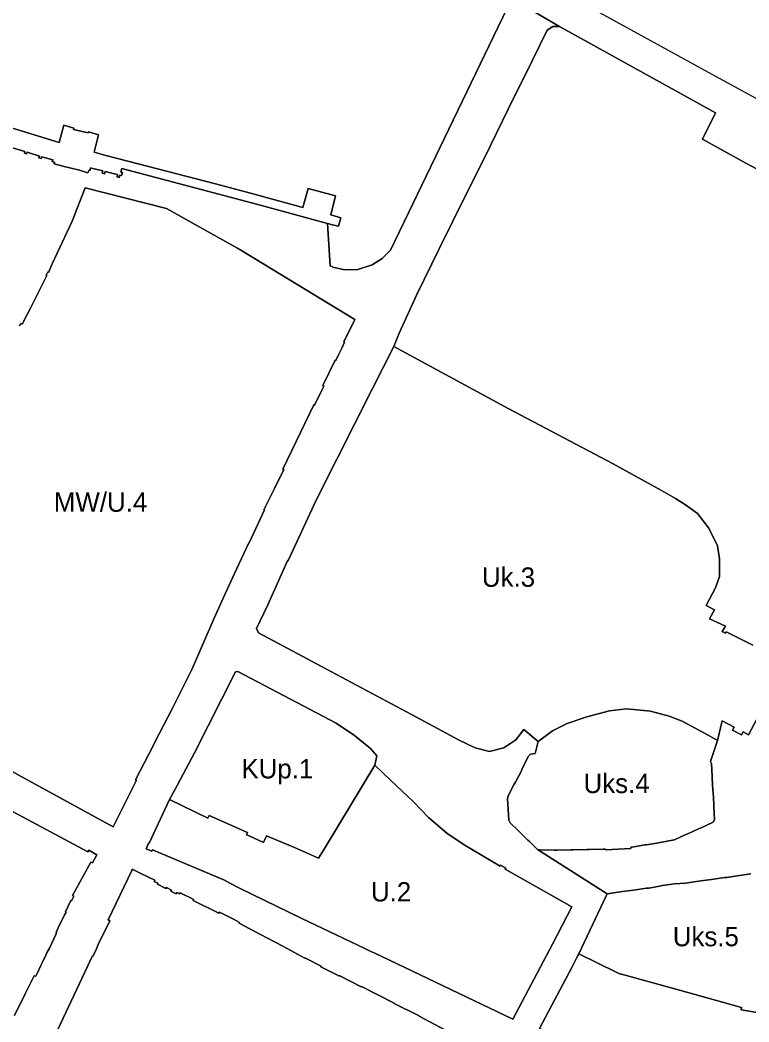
# Model space of a CAD drawing. Extents: x 7423367 to 7424726, y 5546744 to 5548391.
# Drawn here: x 7424194.2 to 7424382.5, y 5547946.7 to 5548205.6 of the extents above; entities that cross this region are included whole.
import ezdxf

# ---------------------------------------------------------------- set-up
doc = ezdxf.new("R2010")
doc.units = 0
doc.layers.add('linie_rozgraniczajace', color=7, linetype='Continuous')
doc.layers.add('oznaczenia_przeznaczen', color=7, linetype='Continuous')

msp = doc.modelspace()

# ---------------------------------------------------------------- linework, layer by layer
at = {"layer": 'linie_rozgraniczajace'}
for points in [[(7424286.01, 5548239.48), (7424370.3, 5548193.14), (7424428.92, 5548161.09)], [(7424319.4, 5548212.3), (7424333.6, 5548203.92), (7424331.83, 5548203.96), (7424330.41, 5548203.01), (7424326.57, 5548195.29), (7424320.43, 5548182.75), (7424314.21, 5548169.98), (7424309.57, 5548160.79), (7424302.51, 5548146.53), (7424296.72, 5548134.67), (7424292.1, 5548124.7), (7424290.77, 5548121.24), (7424285.28, 5548110.4), (7424271.49, 5548083.13), (7424270.21, 5548080.43), (7424263.51, 5548066.1), (7424263.2, 5548065.67), (7424258.24, 5548054.49), (7424255.26, 5548048.35), (7424255.77, 5548047.25), (7424274.69, 5548037.16), (7424295.34, 5548026.14), (7424307.68, 5548019.56), (7424311.77, 5548017.54), (7424315.51, 5548016.62), (7424319.17, 5548017.51), (7424322.26, 5548019.65), (7424324.34, 5548022.28), (7424328.03, 5548019.22), (7424327.33, 5548016.11), (7424326.08, 5548015.94), (7424325.6, 5548015.4), (7424323.96, 5548012.17), (7424323.72, 5548011.63), (7424322.17, 5548008.65), (7424321.89, 5548008.12), (7424320.3, 5548005.11), (7424320.12, 5548004.39), (7424320.5, 5547998.83), (7424320.86, 5547998.18), (7424322.92, 5547996.16), (7424323.34, 5547995.73), (7424325.39, 5547993.72), (7424325.83, 5547993.32), (7424327.93, 5547991.29), (7424345.88, 5547979.8), (7424345.6, 5547979.27), (7424338.61, 5547964.34), (7424338.1, 5547963.38), (7424336.81, 5547960.95), (7424328.44, 5547945.05)], [(7424392.29, 5548163.05), (7424381.71, 5548168.66), (7424370.52, 5548174.87), (7424373.92, 5548181.65), (7424333.6, 5548203.92), (7424319.4, 5548212.3)], [(7424320.01, 5548208.65), (7424289.94, 5548146.16), (7424287.78, 5548144.01), (7424285.2, 5548142.4), (7424281.5, 5548141.18), (7424277.97, 5548141.04), (7424275, 5548141.78), (7424274.88, 5548141.83), (7424274.3, 5548142.07), (7424273.66, 5548153.07), (7424275.24, 5548152.64), (7424276.43, 5548152.32), (7424277.08, 5548154.53), (7424274.49, 5548155.25), (7424275.7, 5548160.19), (7424268.59, 5548162.11), (7424267.27, 5548157.2), (7424253.68, 5548160.86), (7424244.68, 5548163.29), (7424224.71, 5548168.5), (7424216.35, 5548170.65), (7424213.28, 5548171.45), (7424214.4, 5548175.97), (7424211.88, 5548176.74), (7424211.8, 5548176.45), (7424211.73, 5548176.47), (7424208.01, 5548177.35), (7424207.94, 5548177.36), (7424208.03, 5548177.65), (7424205.44, 5548178.42), (7424204.31, 5548173.94), (7424161.51, 5548187.05)], [(7424192.25, 5548172.59), (7424195.42, 5548171.62), (7424195.29, 5548171.19), (7424195.86, 5548171.02), (7424195.99, 5548171.45), (7424199.18, 5548170.47), (7424199.05, 5548170.04), (7424199.62, 5548169.87), (7424199.75, 5548170.3), (7424202.6, 5548169.47), (7424202.47, 5548169.05), (7424203.08, 5548168.86), (7424203, 5548168.45), (7424205.23, 5548167.89), (7424209.49, 5548166.82), (7424211.68, 5548166.15), (7424211.99, 5548166.83), (7424212.25, 5548166.81), (7424212.38, 5548167.4), (7424212.93, 5548167.25), (7424215.17, 5548166.75), (7424215.57, 5548166.65), (7424215.42, 5548166.02), (7424216, 5548165.87), (7424216.14, 5548166.48), (7424216.51, 5548166.38), (7424218.94, 5548165.81), (7424219.35, 5548165.69), (7424219.24, 5548165.08), (7424219.79, 5548164.92), (7424219.99, 5548165.52), (7424220.38, 5548165.44), (7424220.63, 5548166.24), (7424220.22, 5548166.35), (7424220.43, 5548167.27), (7424255.61, 5548157.98), (7424273.66, 5548153.07), (7424274.3, 5548142.07), (7424274.88, 5548141.83), (7424275, 5548141.78), (7424277.97, 5548141.04), (7424281.5, 5548141.18), (7424285.2, 5548142.4), (7424287.78, 5548144.01), (7424289.94, 5548146.16), (7424320.01, 5548208.65)], [(7424383.51, 5548044.09), (7424382.51, 5548044.59), (7424377.18, 5548047.27), (7424376.64, 5548047.55), (7424376.6, 5548047.48), (7424376.45, 5548047.17), (7424375.6, 5548047.63), (7424376.46, 5548049.03), (7424372.31, 5548050.9), (7424373.67, 5548053.19), (7424371.47, 5548054.32), (7424373.87, 5548058.86), (7424374.94, 5548061.81), (7424374.95, 5548066.42), (7424374.37, 5548069.72), (7424372.18, 5548074.33), (7424369.25, 5548078.07), (7424366.15, 5548080.38), (7424363.52, 5548081.95), (7424359.9, 5548084.07), (7424347.49, 5548090.93), (7424320.5, 5548105.13), (7424290.77, 5548121.24), (7424292.1, 5548124.7), (7424296.72, 5548134.67), (7424302.51, 5548146.53), (7424309.57, 5548160.79), (7424314.21, 5548169.98), (7424320.43, 5548182.75), (7424326.57, 5548195.29), (7424330.41, 5548203.01), (7424331.83, 5548203.96), (7424333.6, 5548203.92), (7424373.92, 5548181.65), (7424370.52, 5548174.87), (7424381.71, 5548168.66), (7424392.29, 5548163.05)], [(7424161.51, 5548187.05), (7424204.31, 5548173.94), (7424205.44, 5548178.42), (7424208.03, 5548177.65), (7424207.94, 5548177.36), (7424208.01, 5548177.35), (7424211.73, 5548176.47), (7424211.8, 5548176.45), (7424211.88, 5548176.74), (7424214.4, 5548175.97), (7424213.28, 5548171.45), (7424216.35, 5548170.65), (7424224.71, 5548168.5), (7424244.68, 5548163.29), (7424253.68, 5548160.86), (7424267.27, 5548157.2), (7424268.59, 5548162.11), (7424275.7, 5548160.19), (7424274.49, 5548155.25), (7424277.08, 5548154.53), (7424276.43, 5548152.32), (7424275.24, 5548152.64), (7424273.66, 5548153.07), (7424255.61, 5548157.98), (7424220.43, 5548167.27), (7424220.22, 5548166.35), (7424220.63, 5548166.24), (7424220.38, 5548165.44), (7424219.99, 5548165.52), (7424219.79, 5548164.92), (7424219.24, 5548165.08), (7424219.35, 5548165.69), (7424218.94, 5548165.81), (7424216.51, 5548166.38), (7424216.14, 5548166.48), (7424216, 5548165.87), (7424215.42, 5548166.02), (7424215.57, 5548166.65), (7424215.17, 5548166.75), (7424212.93, 5548167.25), (7424212.38, 5548167.4), (7424212.25, 5548166.81), (7424211.99, 5548166.83), (7424211.68, 5548166.15), (7424209.49, 5548166.82), (7424205.23, 5548167.89), (7424203, 5548168.45), (7424203.08, 5548168.86), (7424202.47, 5548169.05), (7424202.6, 5548169.47), (7424199.75, 5548170.3), (7424199.62, 5548169.87), (7424199.05, 5548170.04), (7424199.18, 5548170.47), (7424195.99, 5548171.45), (7424195.86, 5548171.02), (7424195.29, 5548171.19), (7424195.42, 5548171.62), (7424192.25, 5548172.59)], [(7424194.01, 5548126.61), (7424194.39, 5548127.21), (7424194.73, 5548127.02), (7424196.08, 5548129.68), (7424196.93, 5548131.33), (7424201.05, 5548139.58), (7424200.88, 5548139.69), (7424201.31, 5548140.55), (7424201.55, 5548140.38), (7424202.46, 5548142.66), (7424207.61, 5548153.66), (7424211, 5548162.28), (7424232.05, 5548156.89), (7424243.53, 5548150.49), (7424250.16, 5548146.8), (7424250.46, 5548146.6), (7424250.8, 5548146.38), (7424280.68, 5548128.27), (7424277.85, 5548122.43), (7424278.02, 5548122.37), (7424277.38, 5548121.03), (7424276.38, 5548118.95), (7424275.75, 5548117.62), (7424275.6, 5548117.69), (7424272.41, 5548111.15), (7424272.64, 5548111.01), (7424272.15, 5548109.97), (7424270.28, 5548106.09), (7424270.05, 5548106.21), (7424262.08, 5548089.58), (7424262.32, 5548089.47), (7424259.96, 5548084.56), (7424257.18, 5548079.08), (7424257.3, 5548079.01), (7424253.41, 5548070.51), (7424253.25, 5548070.56), (7424250.78, 5548065.19), (7424250.69, 5548065), (7424248.09, 5548059.42), (7424246.76, 5548056.43), (7424244.34, 5548051.05), (7424238.67, 5548038), (7424233.32, 5548027.25), (7424230.18, 5548021.31), (7424227.56, 5548016.12), (7424224.03, 5548009.31), (7424224.28, 5548009.18), (7424218.21, 5547997.11), (7424195.36, 5548009.65), (7424191.2, 5548011.91)], [(7424191.2, 5548011.91), (7424195.36, 5548009.65), (7424218.21, 5547997.11), (7424224.28, 5548009.18), (7424224.03, 5548009.31), (7424227.56, 5548016.12), (7424230.18, 5548021.31), (7424233.32, 5548027.25), (7424238.67, 5548038), (7424244.34, 5548051.05), (7424246.76, 5548056.43), (7424248.09, 5548059.42), (7424250.69, 5548065), (7424250.78, 5548065.19), (7424253.25, 5548070.56), (7424253.41, 5548070.51), (7424257.3, 5548079.01), (7424257.18, 5548079.08), (7424259.96, 5548084.56), (7424262.32, 5548089.47), (7424262.08, 5548089.58), (7424270.05, 5548106.21), (7424270.28, 5548106.09), (7424272.15, 5548109.97), (7424272.64, 5548111.01), (7424272.41, 5548111.15), (7424275.6, 5548117.69), (7424275.75, 5548117.62), (7424276.38, 5548118.95), (7424277.38, 5548121.03), (7424278.02, 5548122.37), (7424277.85, 5548122.43), (7424280.68, 5548128.27), (7424250.8, 5548146.38), (7424250.46, 5548146.6), (7424250.16, 5548146.8), (7424243.53, 5548150.49), (7424232.05, 5548156.89), (7424211, 5548162.28), (7424207.61, 5548153.66), (7424202.46, 5548142.66), (7424201.55, 5548140.38), (7424201.31, 5548140.55), (7424200.88, 5548139.69), (7424201.05, 5548139.58), (7424196.93, 5548131.33), (7424196.08, 5548129.68), (7424194.73, 5548127.02), (7424194.39, 5548127.21), (7424194.01, 5548126.61)], [(7424384.79, 5548025.3), (7424382.45, 5548020.95), (7424381.04, 5548021.69), (7424380.65, 5548020.94), (7424378.33, 5548022.09), (7424378.73, 5548022.88), (7424375.59, 5548024.51), (7424374.37, 5548019.4), (7424371.96, 5548020.79), (7424365.27, 5548024.43), (7424361.96, 5548025.73), (7424357.13, 5548027.03), (7424350.87, 5548027.61), (7424346.53, 5548027.12), (7424340.6, 5548025.54), (7424335.56, 5548023.85), (7424331.81, 5548021.9), (7424328.03, 5548019.22), (7424324.34, 5548022.28), (7424322.26, 5548019.65), (7424319.17, 5548017.51), (7424315.51, 5548016.62), (7424311.77, 5548017.54), (7424307.68, 5548019.56), (7424295.34, 5548026.14), (7424274.69, 5548037.16), (7424255.77, 5548047.25), (7424255.26, 5548048.35), (7424258.24, 5548054.49), (7424263.2, 5548065.67), (7424263.51, 5548066.1), (7424270.21, 5548080.43), (7424271.49, 5548083.13), (7424285.28, 5548110.4), (7424290.77, 5548121.24), (7424320.5, 5548105.13), (7424347.49, 5548090.93), (7424359.9, 5548084.07), (7424363.52, 5548081.95), (7424366.15, 5548080.38), (7424369.25, 5548078.07), (7424372.18, 5548074.33), (7424374.37, 5548069.72), (7424374.95, 5548066.42), (7424374.94, 5548061.81), (7424373.87, 5548058.86), (7424371.47, 5548054.32), (7424373.67, 5548053.19), (7424372.31, 5548050.9), (7424376.46, 5548049.03), (7424375.6, 5548047.63), (7424376.45, 5548047.17), (7424376.6, 5548047.48), (7424376.64, 5548047.55), (7424377.18, 5548047.27), (7424382.51, 5548044.59), (7424383.51, 5548044.09)], [(7424383.04, 5547984.99), (7424380.09, 5547984.56), (7424379.51, 5547984.47), (7424376.8, 5547984.07), (7424376.21, 5547984.01), (7424373.49, 5547983.61), (7424372.9, 5547983.55), (7424370.11, 5547983.17), (7424369.51, 5547983.07), (7424366.75, 5547982.67), (7424366.13, 5547982.59), (7424363.32, 5547982.43), (7424362.59, 5547982.33), (7424360.16, 5547981.96), (7424359.44, 5547981.83), (7424356.69, 5547981.32), (7424356.06, 5547981.24), (7424353.28, 5547980.87), (7424352.67, 5547980.79), (7424349.88, 5547980.38), (7424349.3, 5547980.3), (7424346.48, 5547979.87), (7424345.88, 5547979.8), (7424327.93, 5547991.29), (7424328.38, 5547991.18), (7424332.24, 5547991.12), (7424332.85, 5547991.12), (7424336.49, 5547991.17), (7424337.1, 5547991.19), (7424340.71, 5547991.25), (7424341.36, 5547991.27), (7424344.87, 5547991.32), (7424345.43, 5547991.32), (7424345.47, 5547991.21), (7424352.04, 5547991.51), (7424352.04, 5547991.84), (7424352.35, 5547991.91), (7424355.61, 5547992.44), (7424356.09, 5547992.5), (7424359.17, 5547993.03), (7424359.63, 5547993.1), (7424362.76, 5547993.65), (7424363.26, 5547993.77), (7424366.26, 5547995.13), (7424366.73, 5547995.32), (7424369.71, 5547996.66), (7424370.19, 5547996.86), (7424373.31, 5547998.37), (7424373.63, 5547998.93), (7424373.49, 5548002.37), (7424373.45, 5548002.91), (7424373.25, 5548006), (7424373.23, 5548006.56), (7424373.04, 5548009.72), (7424373.03, 5548010.26), (7424372.82, 5548013.49), (7424372.57, 5548013.99), (7424374.37, 5548019.4), (7424375.59, 5548024.51), (7424378.73, 5548022.88), (7424378.33, 5548022.09), (7424380.65, 5548020.94), (7424381.04, 5548021.69), (7424382.45, 5548020.95), (7424384.79, 5548025.3)], [(7424192.42, 5548001.04), (7424211.72, 5547990.69), (7424211.93, 5547991.06), (7424214, 5547989.93), (7424212.87, 5547987.81), (7424212.49, 5547988), (7424207.75, 5547979.41), (7424208.05, 5547979.2), (7424207.71, 5547978.52), (7424207.46, 5547978.03), (7424207.3, 5547978.08), (7424205.91, 5547975.19), (7424206.06, 5547975.1), (7424205.66, 5547974.35), (7424204.05, 5547970.99), (7424203.53, 5547969.83), (7424203.59, 5547969.77), (7424203.41, 5547969.28), (7424202.91, 5547968.23), (7424201.75, 5547965.8), (7424201.2, 5547964.72), (7424200.82, 5547963.96), (7424199.78, 5547961.78), (7424199.57, 5547961.33), (7424198.58, 5547959.22), (7424198.24, 5547958.52), (7424197.8, 5547958.67), (7424195.6, 5547954.18), (7424192.76, 5547948.4)], [(7424192.76, 5547948.4), (7424195.6, 5547954.18), (7424197.8, 5547958.67), (7424198.24, 5547958.52), (7424198.58, 5547959.22), (7424199.57, 5547961.33), (7424199.78, 5547961.78), (7424200.82, 5547963.96), (7424201.2, 5547964.72), (7424201.75, 5547965.8), (7424202.91, 5547968.23), (7424203.41, 5547969.28), (7424203.59, 5547969.77), (7424203.53, 5547969.83), (7424204.05, 5547970.99), (7424205.66, 5547974.35), (7424206.06, 5547975.1), (7424205.91, 5547975.19), (7424207.3, 5547978.08), (7424207.46, 5547978.03), (7424207.71, 5547978.52), (7424208.05, 5547979.2), (7424207.75, 5547979.41), (7424212.49, 5547988), (7424212.87, 5547987.81), (7424214, 5547989.93), (7424211.93, 5547991.06), (7424211.72, 5547990.69), (7424192.42, 5548001.04)], [(7424199.05, 5547934.37), (7424209.56, 5547956.66), (7424212.82, 5547963.65), (7424213.04, 5547963.82), (7424213.81, 5547965.46), (7424214.39, 5547966.71), (7424217.36, 5547972.88), (7424216.95, 5547973.11), (7424223.01, 5547985.89), (7424223.15, 5547986.19), (7424223.49, 5547986.02), (7424225, 5547985.28), (7424227.49, 5547984.03), (7424228.99, 5547983.32), (7424228.85, 5547983.03), (7424229.8, 5547982.57), (7424229.67, 5547982.29), (7424231.86, 5547981.21), (7424232.01, 5547981.45), (7424233.27, 5547980.8), (7424233.11, 5547980.49), (7424234.5, 5547979.83), (7424234.67, 5547980.14), (7424235.33, 5547979.81), (7424235.56, 5547980.07), (7424236.39, 5547979.64), (7424238.18, 5547978.78), (7424239.01, 5547978.33), (7424238.91, 5547978.13), (7424245.54, 5547974.84), (7424245.73, 5547975.04), (7424249.64, 5547973.11), (7424250.9, 5547972.42), (7424250.8, 5547972.23), (7424256.16, 5547969.39), (7424262.05, 5547966.26), (7424267.75, 5547963.21), (7424267.95, 5547963.16), (7424271.96, 5547961.11), (7424271.89, 5547960.97), (7424276.52, 5547958.62), (7424276.8, 5547958.62), (7424282.32, 5547955.76), (7424282.41, 5547955.86), (7424290.83, 5547951.6), (7424290.89, 5547951.46), (7424297.34, 5547948.26), (7424297.29, 5547948.18), (7424316.09, 5547938.25)], [(7424316.09, 5547938.25), (7424297.29, 5547948.18), (7424297.34, 5547948.26), (7424290.89, 5547951.46), (7424290.83, 5547951.6), (7424282.41, 5547955.86), (7424282.32, 5547955.76), (7424276.8, 5547958.62), (7424276.52, 5547958.62), (7424271.89, 5547960.97), (7424271.96, 5547961.11), (7424267.95, 5547963.16), (7424267.75, 5547963.21), (7424262.05, 5547966.26), (7424256.16, 5547969.39), (7424250.8, 5547972.23), (7424250.9, 5547972.42), (7424249.64, 5547973.11), (7424245.73, 5547975.04), (7424245.54, 5547974.84), (7424238.91, 5547978.13), (7424239.01, 5547978.33), (7424238.18, 5547978.78), (7424236.39, 5547979.64), (7424235.56, 5547980.07), (7424235.33, 5547979.81), (7424234.67, 5547980.14), (7424234.5, 5547979.83), (7424233.11, 5547980.49), (7424233.27, 5547980.8), (7424232.01, 5547981.45), (7424231.86, 5547981.21), (7424229.67, 5547982.29), (7424229.8, 5547982.57), (7424228.85, 5547983.03), (7424228.99, 5547983.32), (7424227.49, 5547984.03), (7424225, 5547985.28), (7424223.49, 5547986.02), (7424223.15, 5547986.19), (7424223.01, 5547985.89), (7424216.95, 5547973.11), (7424217.36, 5547972.88), (7424214.39, 5547966.71), (7424213.81, 5547965.46), (7424213.04, 5547963.82), (7424212.82, 5547963.65), (7424209.56, 5547956.66), (7424199.05, 5547934.37)], [(7424388.26, 5547948.56), (7424380.54, 5547949.83), (7424380.63, 5547950.44), (7424375.68, 5547951.82), (7424363.05, 5547955.32), (7424350.58, 5547958.76), (7424348.95, 5547959.24), (7424348.19, 5547959.59), (7424338.61, 5547964.34), (7424345.6, 5547979.27), (7424345.88, 5547979.8), (7424346.48, 5547979.87), (7424349.3, 5547980.3), (7424349.88, 5547980.38), (7424352.67, 5547980.79), (7424353.28, 5547980.87), (7424356.06, 5547981.24), (7424356.69, 5547981.32), (7424359.44, 5547981.83), (7424360.16, 5547981.96), (7424362.59, 5547982.33), (7424363.32, 5547982.43), (7424366.13, 5547982.59), (7424366.75, 5547982.67), (7424369.51, 5547983.07), (7424370.11, 5547983.17), (7424372.9, 5547983.55), (7424373.49, 5547983.61), (7424376.21, 5547984.01), (7424376.8, 5547984.07), (7424379.51, 5547984.47), (7424380.09, 5547984.56), (7424383.04, 5547984.99)]]:
    msp.add_lwpolyline(points, dxfattribs=at)
for points in [[(7424226.74, 5547991.45), (7424228.2, 5547990.85), (7424228.36, 5547991.19), (7424246.96, 5547983.33), (7424248.42, 5547982.57), (7424250.88, 5547981.24), (7424267.01, 5547973.46), (7424283.3, 5547965.69), (7424284.84, 5547964.95), (7424285.7, 5547964.57), (7424321.51, 5547947.47), (7424331.74, 5547966.82), (7424336.79, 5547976.44), (7424319.57, 5547986.21), (7424319.7, 5547986.48), (7424318.37, 5547987.2), (7424318.26, 5547986.99), (7424308.92, 5547992.44), (7424304.47, 5547995.52), (7424299.7, 5547999.56), (7424295.72, 5548003.71), (7424290.01, 5548009.13), (7424285.87, 5548013.08), (7424286.38, 5548015.47), (7424284.73, 5548017.39), (7424280.62, 5548020.7), (7424275.86, 5548023.89), (7424250.46, 5548037.25), (7424249.81, 5548037.15), (7424239.27, 5548016.29), (7424234.15, 5548006.69), (7424232.77, 5548004.18), (7424227.55, 5547992.89), (7424227.37, 5547992.92)], [(7424232.77, 5548004.18), (7424234.15, 5548006.69), (7424239.27, 5548016.29), (7424249.81, 5548037.15), (7424250.46, 5548037.25), (7424275.86, 5548023.89), (7424280.62, 5548020.7), (7424284.73, 5548017.39), (7424286.38, 5548015.47), (7424285.87, 5548013.08), (7424272.99, 5547991.82), (7424271.32, 5547989.07), (7424265.13, 5547991.77), (7424257.83, 5547994.78), (7424257.1, 5547993.05), (7424253.52, 5547994.68), (7424252.66, 5547995.07), (7424252.94, 5547995.64), (7424243.05, 5548000.02), (7424242.69, 5547999.37)], [(7424320.12, 5548004.39), (7424320.3, 5548005.11), (7424321.89, 5548008.12), (7424322.17, 5548008.65), (7424323.72, 5548011.63), (7424323.96, 5548012.17), (7424325.6, 5548015.4), (7424326.08, 5548015.94), (7424327.33, 5548016.11), (7424328.03, 5548019.22), (7424331.81, 5548021.9), (7424335.56, 5548023.85), (7424340.6, 5548025.54), (7424346.53, 5548027.12), (7424350.87, 5548027.61), (7424357.13, 5548027.03), (7424361.96, 5548025.73), (7424365.27, 5548024.43), (7424371.96, 5548020.79), (7424374.37, 5548019.4), (7424372.57, 5548013.99), (7424372.82, 5548013.49), (7424373.03, 5548010.26), (7424373.04, 5548009.72), (7424373.23, 5548006.56), (7424373.25, 5548006), (7424373.45, 5548002.91), (7424373.49, 5548002.37), (7424373.63, 5547998.93), (7424373.31, 5547998.37), (7424370.19, 5547996.86), (7424369.71, 5547996.66), (7424366.73, 5547995.32), (7424366.26, 5547995.13), (7424363.26, 5547993.77), (7424362.76, 5547993.65), (7424359.63, 5547993.1), (7424359.17, 5547993.03), (7424356.09, 5547992.5), (7424355.61, 5547992.44), (7424352.35, 5547991.91), (7424352.04, 5547991.84), (7424352.04, 5547991.51), (7424345.47, 5547991.21), (7424345.43, 5547991.32), (7424344.87, 5547991.32), (7424341.36, 5547991.27), (7424340.71, 5547991.25), (7424337.1, 5547991.19), (7424336.49, 5547991.17), (7424332.85, 5547991.12), (7424332.24, 5547991.12), (7424328.38, 5547991.18), (7424327.93, 5547991.29), (7424325.83, 5547993.32), (7424325.39, 5547993.72), (7424323.34, 5547995.73), (7424322.92, 5547996.16), (7424320.86, 5547998.18), (7424320.5, 5547998.83)], [(7424226.74, 5547991.45), (7424227.37, 5547992.92), (7424227.55, 5547992.89), (7424232.77, 5548004.18), (7424242.69, 5547999.37), (7424243.05, 5548000.02), (7424252.94, 5547995.64), (7424252.66, 5547995.07), (7424253.52, 5547994.68), (7424257.1, 5547993.05), (7424257.83, 5547994.78), (7424265.13, 5547991.77), (7424271.32, 5547989.07), (7424272.99, 5547991.82), (7424285.87, 5548013.08), (7424290.01, 5548009.13), (7424295.72, 5548003.71), (7424299.7, 5547999.56), (7424304.47, 5547995.52), (7424308.92, 5547992.44), (7424318.26, 5547986.99), (7424318.37, 5547987.2), (7424319.7, 5547986.48), (7424319.57, 5547986.21), (7424336.79, 5547976.44), (7424331.74, 5547966.82), (7424321.51, 5547947.47), (7424285.7, 5547964.57), (7424284.84, 5547964.95), (7424283.3, 5547965.69), (7424267.01, 5547973.46), (7424250.88, 5547981.24), (7424248.42, 5547982.57), (7424246.96, 5547983.33), (7424228.36, 5547991.19), (7424228.2, 5547990.85)], [(7424328.44, 5547945.05), (7424336.81, 5547960.95), (7424338.1, 5547963.38), (7424338.61, 5547964.34), (7424348.19, 5547959.59), (7424348.95, 5547959.24), (7424350.58, 5547958.76), (7424363.05, 5547955.32), (7424375.68, 5547951.82), (7424380.63, 5547950.44), (7424380.54, 5547949.83), (7424388.26, 5547948.56), (7424388.22, 5547948.28), (7424385.9, 5547931.86), (7424386.56, 5547931.79), (7424385.59, 5547924.92), (7424379.57, 5547921.57), (7424373.24, 5547924.45), (7424373.56, 5547925.07), (7424348.32, 5547936.48), (7424348.05, 5547935.98), (7424338.85, 5547940.14), (7424338.9, 5547940.31)]]:
    msp.add_lwpolyline(points, close=True, dxfattribs=at)

# ---------------------------------------------------------------- texts
at = {"layer": 'oznaczenia_przeznaczen'}
for s, p in [('MW/U.4', (7424202.9, 5548078.55)), ('Uk.3', (7424313.53, 5548059.17)), ('KUp.1', (7424251.37, 5548009.65)), ('Uks.4', (7424339.79, 5548005.85)), ('U.2', (7424284.85, 5547977.84)), ('Uks.5', (7424362.85, 5547966.27))]:
    msp.add_text(s, height=5, dxfattribs=at).set_placement(p)

doc.saveas('drawing.dxf')
